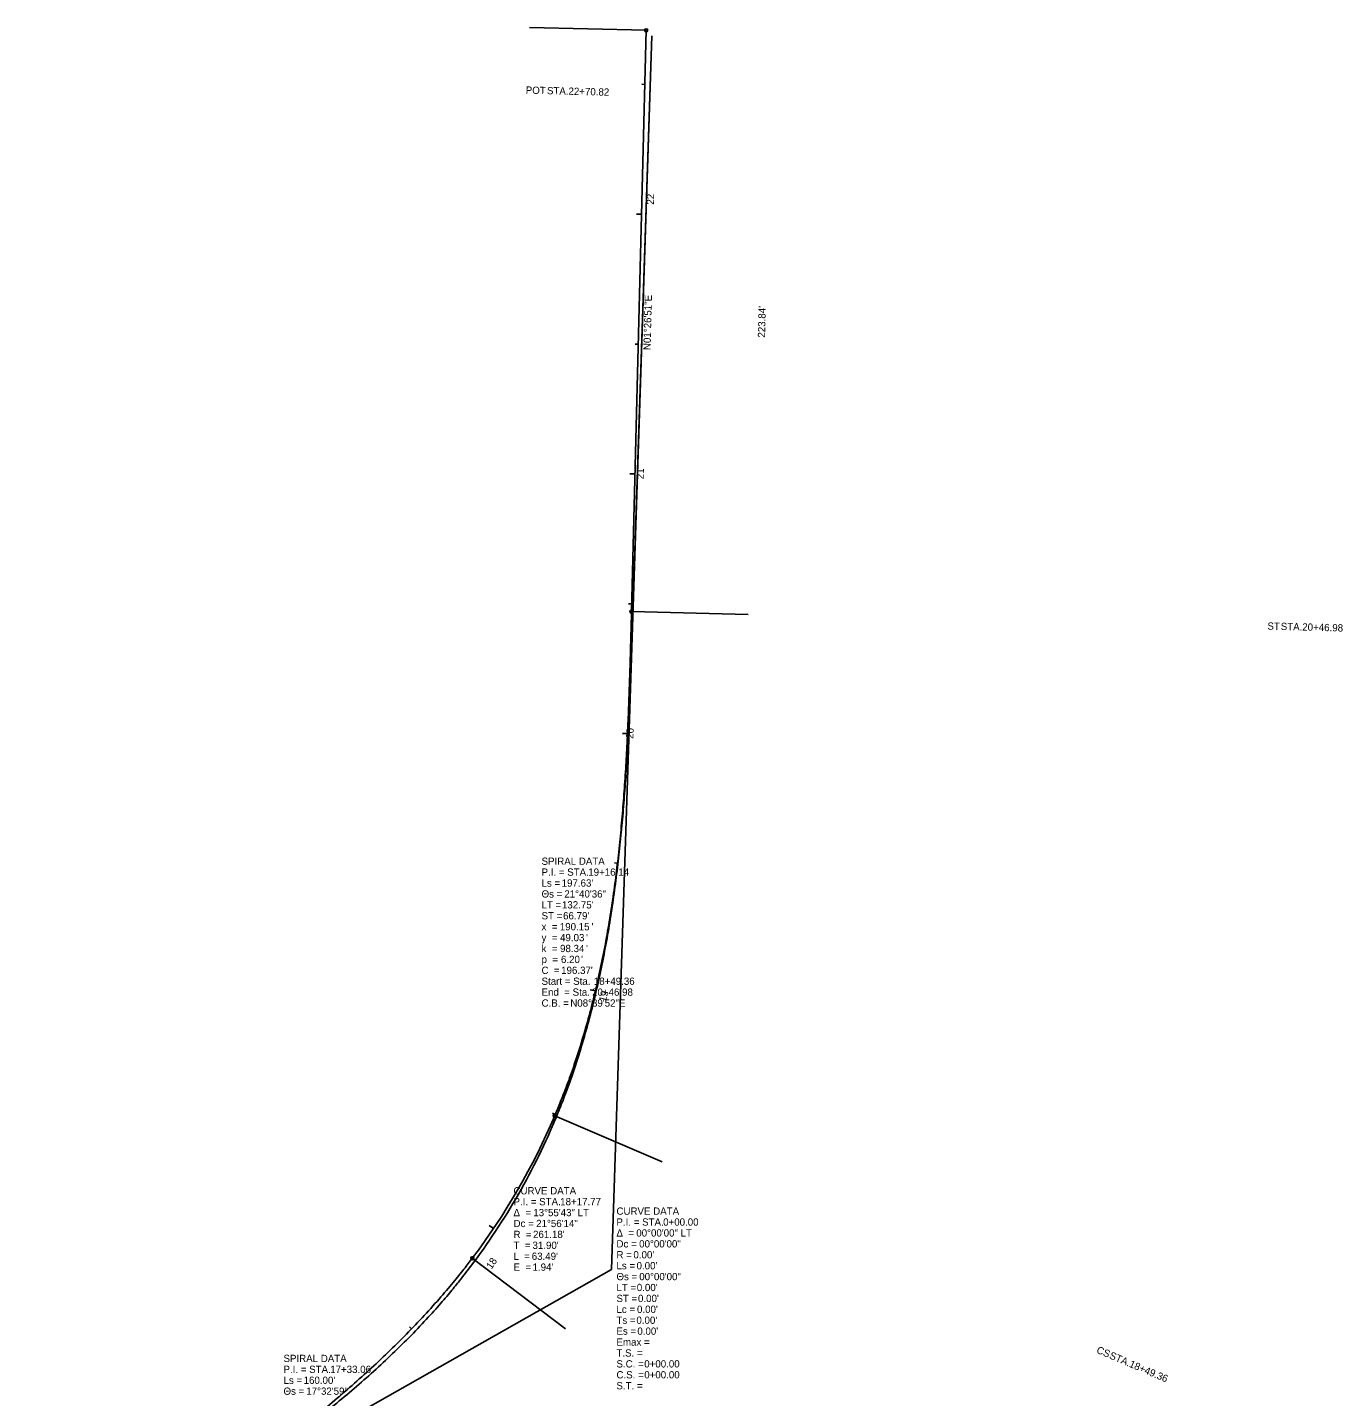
# Model space of a CAD drawing. Extents: x 1504629 to 1506299, y 325931 to 328016.
# Drawn here: x 1504923 to 1505430, y 327489 to 328016 of the extents above; entities that cross this region are included whole.
import ezdxf

# ---------------------------------------------------------------- set-up
doc = ezdxf.new("R2010")
doc.units = 0
for name, color, linetype in [('GE_X_Alignment', 7, 'Continuous'), ('GE_X_Alignment_100_Bearings', 7, 'Continuous'), ('GE_X_Alignment_100_Cardinal_Points', 7, 'Continuous'), ('GE_X_Alignment_100_Curve_Data', 7, 'Continuous'), ('GE_X_Alignment_100_Distances', 7, 'Continuous'), ('GE_X_Alignment_100_Stations', 7, 'Continuous'), ('SC_Scratch7', 7, 'Continuous'), ('SC_Scratch8', 7, 'Continuous')]:
    doc.layers.add(name, color=color, linetype=linetype)

msp = doc.modelspace()

# ---------------------------------------------------------------- linework, layer by layer
at = {"layer": 'GE_X_Alignment'}
msp.add_line((1505156.04, 327791.54), (1505161.69, 328015.31), dxfattribs=at)
msp.add_arc((1504886.26, 327699.98), 261.18, 322.947, 336.8756, dxfattribs=at)
for points in [[(1505126.46, 327597.41), (1505127.1, 327598.93), (1505128.37, 327601.97), (1505130.78, 327608.1), (1505133.6, 327615.84), (1505136.66, 327625.23), (1505139.41, 327634.72), (1505141.88, 327644.29), (1505144.07, 327653.93), (1505146.01, 327663.62), (1505147.71, 327673.35), (1505149.19, 327683.12), (1505150.46, 327692.92), (1505151.55, 327702.75), (1505152.47, 327712.58), (1505153.24, 327722.44), (1505153.89, 327732.3), (1505154.42, 327742.16), (1505154.85, 327752.03), (1505155.21, 327761.91), (1505155.52, 327771.79), (1505155.74, 327780.02), (1505155.91, 327786.6), (1505156, 327789.9), (1505156.04, 327791.54)], [(1504974.89, 327437.57), (1504976.25, 327438.53), (1504978.97, 327440.47), (1504984.4, 327444.33), (1504991.18, 327449.17), (1504999.29, 327455.02), (1505007.36, 327460.93), (1505015.37, 327466.92), (1505023.31, 327473), (1505031.16, 327479.2), (1505038.91, 327485.52), (1505046.53, 327491.99), (1505054.01, 327498.63), (1505061.33, 327505.44), (1505068.47, 327512.44), (1505075.41, 327519.65), (1505082.12, 327527.07), (1505087.5, 327533.43), (1505091.66, 327538.64), (1505093.7, 327541.28), (1505094.7, 327542.61)]]:
    msp.add_open_spline(points, degree=3, dxfattribs=at)
at = {"layer": 'GE_X_Alignment_100_Cardinal_Points'}
for p, q in [((1505161.69, 328015.31), (1505116.71, 328016.44)), ((1505156.04, 327791.54), (1505201.02, 327790.4)), ((1505126.46, 327597.41), (1505167.84, 327579.74)), ((1505094.7, 327542.61), (1505130.62, 327515.49))]:
    msp.add_line(p, q, dxfattribs=at)
for centre in [(1505161.69, 328015.31), (1505156.04, 327791.54), (1505126.46, 327597.41), (1505094.7, 327542.61)]:
    msp.add_circle(centre, 0.6, dxfattribs=at)
at = {"layer": 'GE_X_Alignment_100_Stations'}
for p, q in [((1505161.17, 327994.5), (1505159.97, 327994.53)), ((1505159.9, 327944.51), (1505157.9, 327944.56)), ((1505159.9, 327944.51), (1505158.7, 327944.54)), ((1505158.64, 327894.53), (1505157.44, 327894.56)), ((1505157.38, 327844.54), (1505155.38, 327844.59)), ((1505157.38, 327844.54), (1505156.18, 327844.57)), ((1505156.11, 327794.56), (1505154.91, 327794.59)), ((1505154.52, 327744.59), (1505152.52, 327744.68)), ((1505154.52, 327744.59), (1505153.32, 327744.64)), ((1505150.65, 327694.75), (1505149.46, 327694.89)), ((1505142.12, 327645.51), (1505140.18, 327645.97)), ((1505142.12, 327645.51), (1505140.96, 327645.79)), ((1505126.71, 327598), (1505125.6, 327598.47)), ((1505102.91, 327554.12), (1505101.25, 327555.23)), ((1505102.91, 327554.12), (1505101.92, 327554.79)), ((1505071.33, 327515.43), (1505070.47, 327516.27))]:
    msp.add_line(p, q, dxfattribs=at)
at = {"layer": 'SC_Scratch7'}
for p, q in [((1505148.27, 327538.35), (1505163.89, 328013.2)), ((1504644.71, 327252.82), (1505148.27, 327538.35))]:
    msp.add_line(p, q, dxfattribs=at)
at = {"layer": 'SC_Scratch8'}
msp.add_line((1505156.48, 327787.74), (1505163.89, 328013.2), dxfattribs=at)
msp.add_arc((1504885.82, 327697.07), 261.18, 321.4909, 336.1784, dxfattribs=at)
for points in [[(1505124.75, 327591.59), (1505125.42, 327593.11), (1505126.74, 327596.17), (1505129.26, 327602.35), (1505132.2, 327610.15), (1505135.4, 327619.62), (1505138.29, 327629.2), (1505140.89, 327638.85), (1505143.2, 327648.58), (1505145.26, 327658.37), (1505147.07, 327668.2), (1505148.66, 327678.08), (1505150.04, 327687.98), (1505151.22, 327697.91), (1505152.24, 327707.86), (1505153.1, 327717.82), (1505153.83, 327727.8), (1505154.45, 327737.78), (1505154.97, 327747.77), (1505155.41, 327757.76), (1505155.8, 327767.75), (1505156.09, 327776.08), (1505156.31, 327782.74), (1505156.42, 327786.07), (1505156.48, 327787.74)], [(1504931.21, 327415.27), (1504932.66, 327416.09), (1504935.56, 327417.74), (1504941.36, 327421.03), (1504948.6, 327425.15), (1504957.27, 327430.13), (1504965.91, 327435.17), (1504974.51, 327440.26), (1504983.07, 327445.44), (1504991.56, 327450.72), (1504999.98, 327456.11), (1505008.32, 327461.63), (1505016.56, 327467.3), (1505024.7, 327473.12), (1505032.71, 327479.11), (1505040.57, 327485.28), (1505048.29, 327491.64), (1505055.83, 327498.21), (1505063.18, 327505), (1505070.31, 327512), (1505077.22, 327519.24), (1505082.76, 327525.46), (1505087.06, 327530.56), (1505089.16, 327533.15), (1505090.2, 327534.45)]]:
    msp.add_open_spline(points, degree=3, dxfattribs=at)

# ---------------------------------------------------------------- texts
at = {"layer": 'GE_X_Alignment_100_Bearings'}
msp.add_text('N01°26\'51"E', height=2.8, rotation=88.5524, dxfattribs=at).set_placement((1505163.38, 327892.19))
at = {"layer": 'GE_X_Alignment_100_Cardinal_Points'}
for s, rotation, p in [('POT', 358.5524, (1505115.28, 327990.93)), (' STA. ', 358.5524, (1505122.41, 327990.75)), ('22+70.82', 358.5524, (1505131.73, 327990.51)), ('ST', 358.5524, (1505400.92, 327784.6)), (' STA. ', 358.5524, (1505405.03, 327784.5)), ('20+46.98', 358.5524, (1505414.35, 327784.26)), ('CS', 336.8756, (1505334.88, 327506.31)), (' STA. ', 336.8756, (1505338.89, 327504.59)), ('18+49.36', 336.8756, (1505347.46, 327500.93))]:
    msp.add_text(s, height=2.8, rotation=rotation, dxfattribs=at).set_placement(p)
at = {"layer": 'GE_X_Alignment_100_Curve_Data'}
for s, p in [('SPIRAL DATA', (1505121.39, 327694.07)), ('P.I. = STA. ', (1505121.39, 327689.87)), ('Ls = ', (1505121.39, 327685.67)), ("197.63'", (1505129.14, 327685.67)), ('19+16.14', (1505139.38, 327689.87)), ('Θs = ', (1505121.39, 327681.47)), ('21°40\'36"', (1505130.17, 327681.47)), ('LT = ', (1505121.39, 327677.27)), ("132.75'", (1505129.24, 327677.27)), ('ST = ', (1505121.39, 327673.07)), ("66.79'", (1505129.69, 327673.07)), ('y  = ', (1505121.39, 327664.67)), ('x  = ', (1505121.39, 327668.87)), ('49.03', (1505128.52, 327664.67)), ('190.15', (1505128.42, 327668.87)), ("'", (1505138.54, 327664.67)), ("'", (1505140.67, 327668.87)), ('k  = ', (1505121.39, 327660.47)), ('98.34', (1505128.52, 327660.47)), ("'", (1505138.54, 327660.47)), ('p  = ', (1505121.39, 327656.27)), ('6.20', (1505128.87, 327656.27)), ("'", (1505136.65, 327656.27)), ('C  = ', (1505121.39, 327652.07)), ("196.37'", (1505128.94, 327652.07)), ('Start = Sta. ', (1505121.39, 327647.87)), ('End  = Sta. ', (1505121.39, 327643.67)), ('20+46.98', (1505140.85, 327643.67)), ('18+49.36', (1505141.54, 327647.87)), ('C.B. = ', (1505121.39, 327639.47)), ('N08°39\'52"E', (1505132.46, 327639.47)), ('CURVE DATA', (1505110.58, 327567.21)), ('Δ  = ', (1505110.58, 327558.81)), ('P.I. = STA. ', (1505110.58, 327563.01)), ('13°55\'43" LT', (1505118.22, 327558.81)), ('18+17.77', (1505128.57, 327563.01)), ('CURVE DATA', (1505150.24, 327559.37)), ('Dc = ', (1505110.58, 327554.61)), ('21°56\'14"', (1505119.32, 327554.61)), ('P.I. = STA. ', (1505150.24, 327555.17)), ('0+00.00', (1505168.23, 327555.17)), ('R  = ', (1505110.58, 327550.41)), ("261.18'", (1505118.11, 327550.41)), ('Δ  = ', (1505150.24, 327550.97)), ('00°00\'00" LT', (1505157.89, 327550.97)), ('T  = ', (1505110.58, 327546.21)), ("31.90'", (1505117.9, 327546.21)), ('Dc = ', (1505150.24, 327546.77)), ('R = ', (1505150.24, 327542.57)), ("0.00'", (1505156.78, 327542.57)), ('00°00\'00"', (1505158.99, 327546.77)), ('L  = ', (1505110.58, 327542.01)), ('E  = ', (1505110.58, 327537.81)), ("63.49'", (1505117.61, 327542.01)), ("1.94'", (1505117.92, 327537.81)), ('Ls = ', (1505150.24, 327538.37)), ("0.00'", (1505157.99, 327538.37)), ('Θs = ', (1505150.24, 327534.17)), ('00°00\'00"', (1505159.03, 327534.17)), ('LT = ', (1505150.24, 327529.97)), ("0.00'", (1505158.09, 327529.97)), ('ST = ', (1505150.24, 327525.77)), ('Lc = ', (1505150.24, 327521.57)), ("0.00'", (1505158.16, 327521.57)), ("0.00'", (1505158.54, 327525.77)), ('Ts = ', (1505150.24, 327517.37)), ("0.00'", (1505157.93, 327517.37)), ('Es = ', (1505150.24, 327513.17)), ("0.00'", (1505158.29, 327513.17)), ('Emax = ', (1505150.24, 327508.97)), ('SPIRAL DATA', (1505022, 327502.66)), ('T.S. = ', (1505150.24, 327504.77)), ('S.C. = ', (1505150.24, 327500.57)), ('0+00.00', (1505160.95, 327500.57)), ('P.I. = STA. ', (1505022, 327498.46)), ('17+33.06', (1505039.99, 327498.46)), ('C.S. = ', (1505150.24, 327496.37)), ('0+00.00', (1505160.95, 327496.37)), ('Θs = ', (1505022, 327490.06)), ('Ls = ', (1505022, 327494.26)), ("160.00'", (1505029.75, 327494.26)), ('17°32\'59"', (1505030.78, 327490.06)), ('S.T. = ', (1505150.24, 327492.17))]:
    msp.add_text(s, height=2.8, dxfattribs=at).set_placement(p)
at = {"layer": 'GE_X_Alignment_100_Distances'}
msp.add_text("223.84'", height=2.8, rotation=88.5524, dxfattribs=at).set_placement((1505207.47, 327896.99))
at = {"layer": 'GE_X_Alignment_100_Stations'}
for s, rotation, p in [('22', 88.5524, (1505164.66, 327948.19)), ('21', 88.5524, (1505160.71, 327842.5)), ('20', 87.3274, (1505156.72, 327742.55)), ('19', 76.562, (1505146.15, 327641.15)), ('18', 56.0483, (1505102.11, 327538.18))]:
    msp.add_text(s, height=2.8, rotation=rotation, dxfattribs=at).set_placement(p)

doc.saveas('drawing.dxf')
